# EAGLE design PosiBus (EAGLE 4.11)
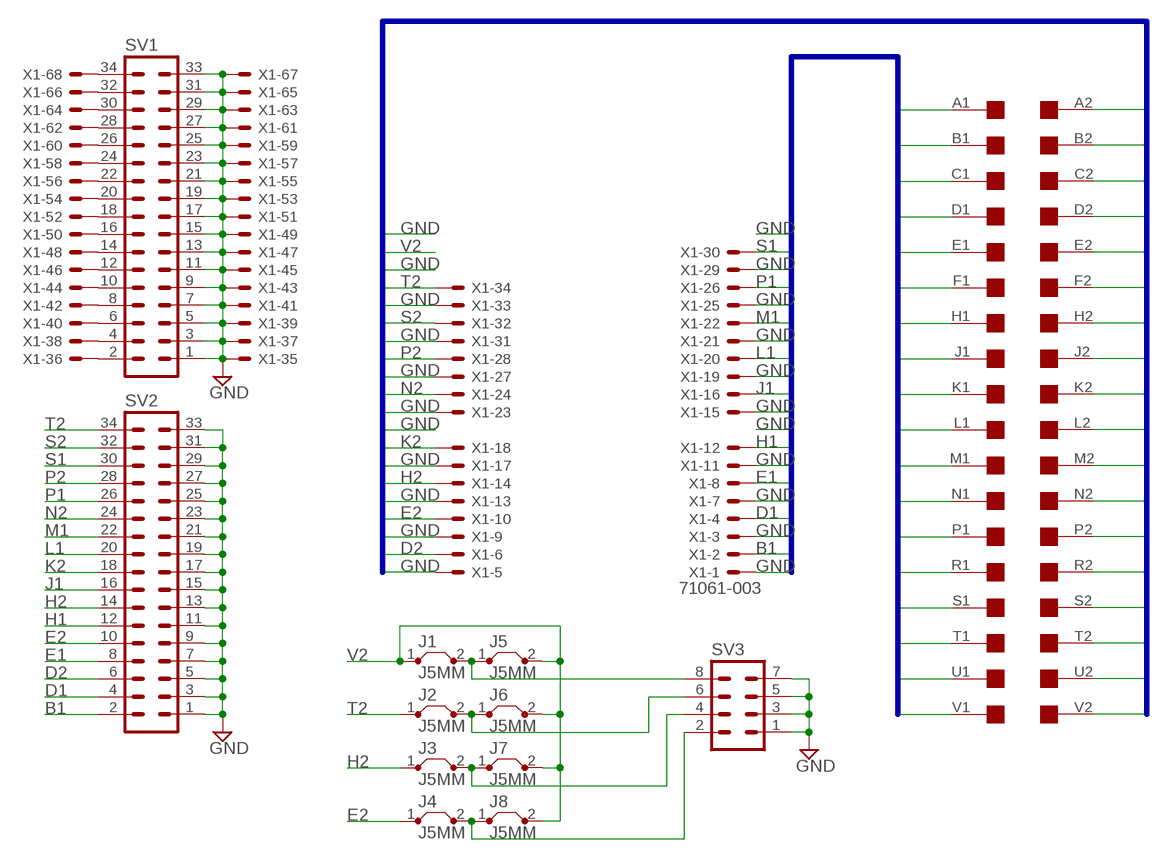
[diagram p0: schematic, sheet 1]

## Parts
J1  J5MM  [05]
J2  J5MM  [05]
J3  J5MM  [05]
J4  J5MM  [05]
J5  J5MM  [05]
J6  J5MM  [05]
J7  J5MM  [05]
J8  J5MM  [05]
SV1  ML34  [ML34]
SV2  ML34  [ML34]
SV3  MA04-2  [MA04-2]
U$1  DEC-FLIPCHIP  [DEC-FLIPCHIP]
X1  71061-003  [71061-0003]

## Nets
A2: U$1.A2
B1: SV2.2 U$1.B1 X1.2
B2: U$1.B2
D1: SV2.4 U$1.D1 X1.4
D2: SV2.6 U$1.D2 X1.6
E1: SV2.8 U$1.E1 X1.8
E2: J4.1 SV2.10 U$1.E2 X1.10
GND [Ground]: SV1.1 SV1.3 SV1.5 SV1.7 SV1.9 SV1.11 SV1.13 SV1.15 SV1.17 SV1.19 SV1.21 SV1.23 SV1.25 SV1.27 SV1.29 SV1.31 SV1.33 SV2.1 SV2.3 SV2.5 SV2.7 SV2.9 SV2.11 SV2.13 SV2.15 SV2.17 SV2.19 SV2.21 SV2.23 SV2.25 SV2.27 SV2.29 SV2.31 SV2.33 SV3.1 SV3.3 SV3.5 SV3.7 U$1.A1 U$1.C1 U$1.C2 U$1.F1 U$1.F2 U$1.J2 U$1.K1 U$1.L2 U$1.M2 U$1.N1 U$1.R1 U$1.R2 U$1.T1 U$1.U2 X1.1 X1.3 X1.5 X1.7 X1.9 X1.11 X1.13 X1.15 X1.17 X1.19 X1.21 X1.23 X1.25 X1.27 X1.29 X1.31 X1.33 X1.35 X1.37 X1.39 X1.41 X1.43 X1.45 X1.47 X1.49 X1.51 X1.53 X1.55 X1.57 X1.59 X1.61 X1.63 X1.65 X1.67
H1: SV2.12 U$1.H1 X1.12
H2: J3.1 SV2.14 U$1.H2 X1.14
J1: SV2.16 U$1.J1 X1.16
K2: SV2.18 U$1.K2 X1.18
L1: SV2.20 U$1.L1 X1.20
M1: SV2.22 U$1.M1 X1.22
N2: SV2.24 U$1.N2 X1.24
N$1: SV1.34 X1.68
N$2: SV1.4 X1.38
N$3: SV1.32 X1.66
N$4: SV1.30 X1.64
N$5: SV1.28 X1.62
N$6: SV1.26 X1.60
N$7: SV1.2 X1.36
N$8: J1.2 J5.1 SV3.8
N$9: J2.2 J6.1 SV3.6
N$10: J3.2 J7.1 SV3.4
N$11: SV1.24 X1.58
N$12: J4.2 J8.1 SV3.2
N$13: SV1.22 X1.56
N$14: SV1.20 X1.54
N$15: SV1.18 X1.52
N$16: SV1.16 X1.50
N$17: SV1.14 X1.48
N$23: SV1.12 X1.46
N$25: SV1.10 X1.44
N$27: SV1.8 X1.42
N$28: SV1.6 X1.40
P1: SV2.26 U$1.P1 X1.26
P2: SV2.28 U$1.P2 X1.28
S1: SV2.30 U$1.S1 X1.30
S2: SV2.32 U$1.S2 X1.32
T2: J2.1 SV2.34 U$1.T2 X1.34
U1: U$1.U1
V1: U$1.V1
V2: J1.1 J5.2 J6.2 J7.2 J8.2 U$1.V2

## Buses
A1,B1,C1,D1,E1,F1,H1,J1,K1,L1,M1,N1,P1,R1,S1,T1,U1,V1
A2,B2,C2,D2,E2,F2,H2,J2,K2,L2,M2,N2,P2,R2,S2,T2,U2,V2

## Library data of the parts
J1-J8 = jumper:J: Bridge
SV1 SV2 = con-harting-ml:ML34: HARTING
SV3 = con-lstb:MA04-2: PIN HEADER
U$1 = con-dec:DEC-FLIPCHIP: DEC Flip-Chip single card fingers
X1 = con-molex:71061-003: CONNECTOR 68-pin 1.27mm (.050 inch) pitch SCSI+ unshielded receptacle right angle all plastic

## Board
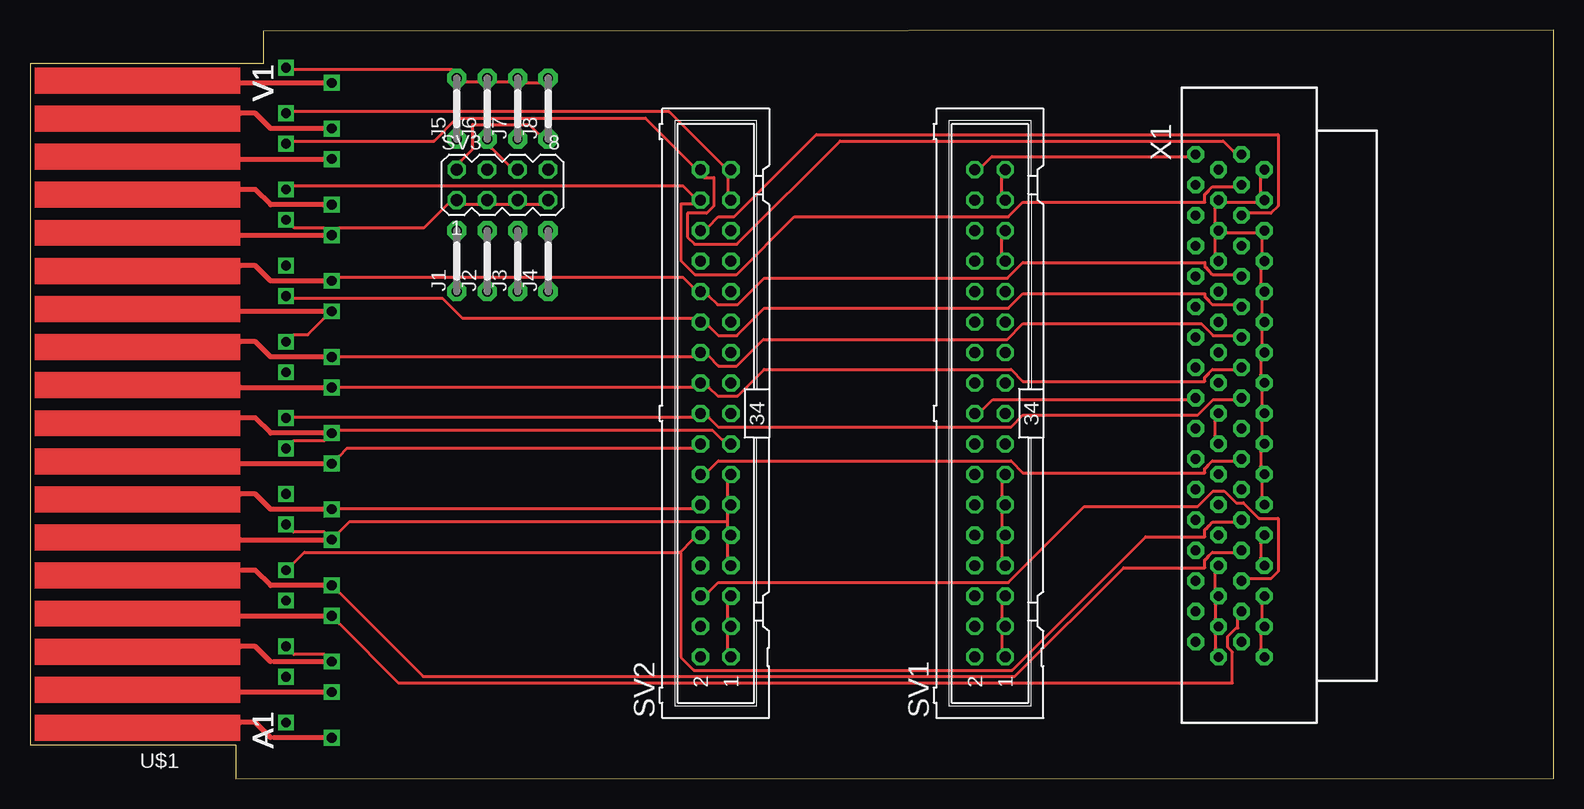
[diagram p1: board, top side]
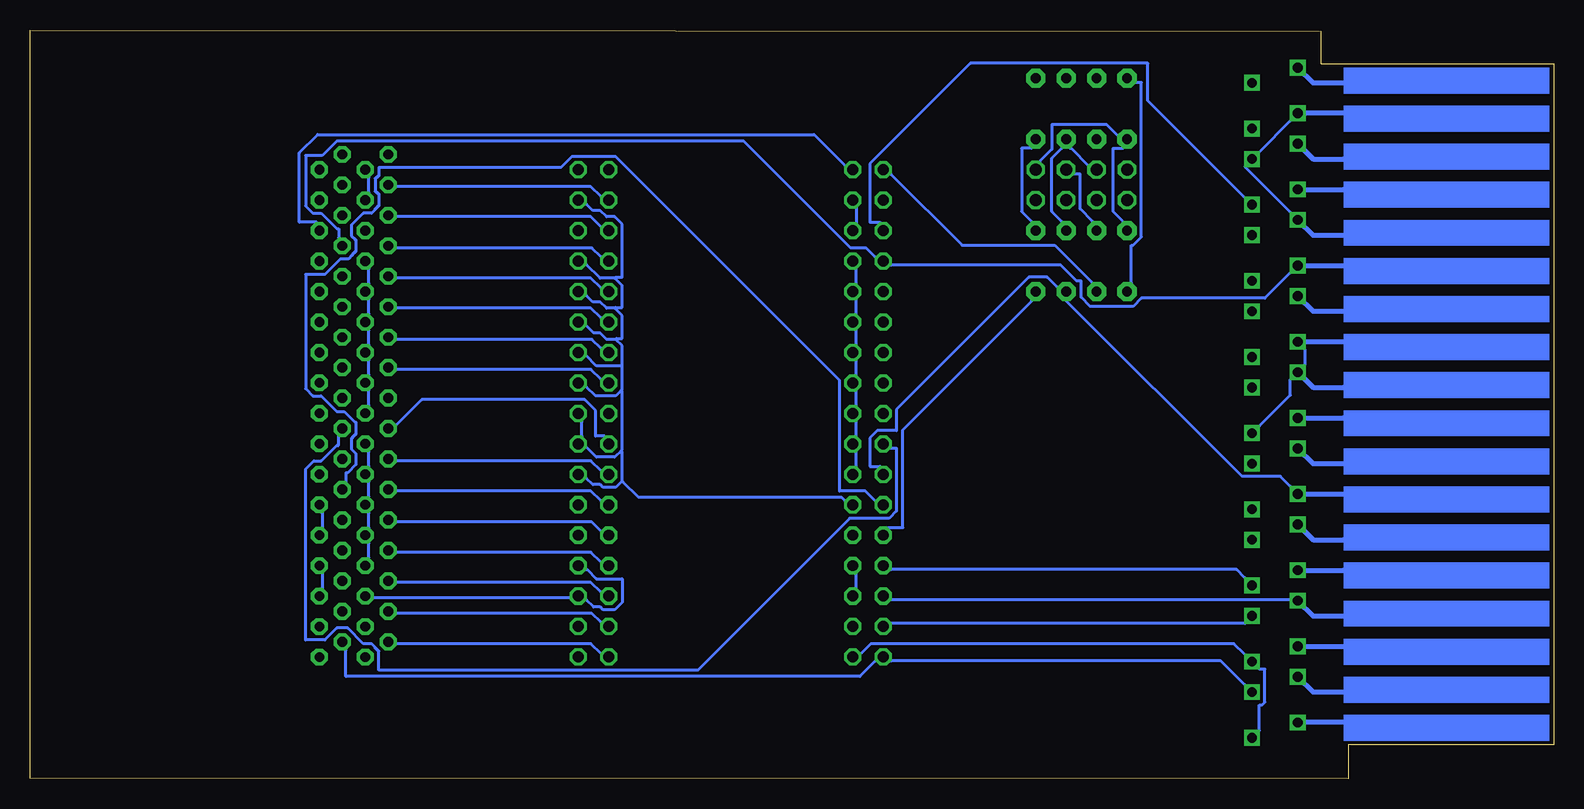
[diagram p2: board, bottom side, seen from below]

Size 126.98 x 62.45 mm. Coordinates in mm from the lower left corner, seen from the top.
Outline: 0,2.83 17.14,2.83 17.14,0 126.98,0.04 126.98,62.45 19.43,62.36 19.43,59.65 0,59.65 0,2.83
Copper layers (1*16): Top 0.035mm / dielectric 1.5mm / Bottom 0.035mm
Design rules "10mils": minimum track width 10mil, minimum drill 24mil, track to track 10mil, track to pad 10mil, pad to pad 10mil, via to via 10mil, smd to smd 10mil, copper to edge 40mil, drill to drill 10mil, minimum pad ring 10mil, minimum via ring 8mil, stop-mask expansion 0mil, vias tented up to drill 0mil, thermal gap 10mil

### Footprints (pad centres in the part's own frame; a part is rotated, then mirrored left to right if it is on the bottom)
05 = drill 0.813 pad 1.6 octagon: 1 -2.54,0; 2 2.54,0
ML34 = drill 0.914 octagon: 1 -20.32,-1.27; 2 -20.32,1.27; 3 -17.78,-1.27; 4 -17.78,1.27; 5 -15.24,-1.27; 6 -15.24,1.27; 7 -12.7,-1.27; 8 -12.7,1.27; 9 -10.16,-1.27; 10 -10.16,1.27; 11 -7.62,-1.27; 12 -7.62,1.27; 13 -5.08,-1.27; 14 -5.08,1.27; 15 -2.54,-1.27; 16 -2.54,1.27; 17 0,-1.27; 18 0,1.27; 19 2.54,-1.27; 20 2.54,1.27; 21 5.08,-1.27; 22 5.08,1.27; 23 7.62,-1.27; 24 7.62,1.27; 25 10.16,-1.27; 26 10.16,1.27; 27 12.7,-1.27; 28 12.7,1.27; 29 15.24,-1.27; 30 15.24,1.27; 31 17.78,-1.27; 32 17.78,1.27; 33 20.32,-1.27; 34 20.32,1.27
MA04-2 = drill 1.016 octagon: 1 -3.81,-1.27; 2 -3.81,1.27; 3 -1.27,-1.27; 4 -1.27,1.27; 5 1.27,-1.27; 6 1.27,1.27; 7 3.81,-1.27; 8 3.81,1.27
DEC-FLIPCHIP = drill 0.813 square: A1 -7.62,27.94; A2 -3.81,26.67; B1 -7.62,24.13; B2 -3.81,22.86; C1 -7.62,21.59; C2 -3.81,20.32; D1 -7.62,17.78; D2 -3.81,16.51; E1 -7.62,15.24; E2 -3.81,13.97; F1 -7.62,11.43; F2 -3.81,10.16; H1 -7.62,8.89; H2 -3.81,7.62; J1 -7.62,5.08; J2 -3.81,3.81; K1 -7.62,2.54; K2 -3.81,1.27; L1 -7.62,-1.27; L2 -3.81,-2.54; M1 -7.62,-3.81; M2 -3.81,-5.08; N1 -7.62,-7.62; N2 -3.81,-8.89; P1 -7.62,-10.16; P2 -3.81,-11.43; R1 -7.62,-13.97; R2 -3.81,-15.24; S1 -7.62,-16.51; S2 -3.81,-17.78; T1 -7.62,-20.32; T2 -3.81,-21.59; U1 -7.62,-22.86; U2 -3.81,-24.13; V1 -7.62,-26.67; V2 -3.81,-27.94
71061-0003 = drill 0.813 pad 1.397 octagon: 1 20.955,0; 2 19.685,-1.91; 3 18.415,0; 4 17.145,-1.91; 5 15.875,0; 6 14.605,-1.91; 7 13.335,0; 8 12.065,-1.91; 9 10.795,0; 10 9.525,-1.91; 11 8.255,0; 12 6.985,-1.91; 13 5.715,0; 14 4.445,-1.91; 15 3.175,0; 16 1.905,-1.91; 17 0.635,0; 18 -0.635,-1.91; 19 -1.905,0; 20 -3.175,-1.91; 21 -4.445,0; 22 -5.715,-1.91; 23 -6.985,0; 24 -8.255,-1.91; 25 -9.525,0; 26 -10.795,-1.91; 27 -12.065,0; 28 -13.335,-1.91; 29 -14.605,0; 30 -15.875,-1.91; 31 -17.145,0; 32 -18.415,-1.91; 33 -19.685,0; 34 -20.955,-1.91; 35 20.955,-3.82; 36 19.685,-5.73; 37 18.415,-3.82; 38 17.145,-5.73; 39 15.875,-3.82; 40 14.605,-5.73; 41 13.335,-3.82; 42 12.065,-5.73; 43 10.795,-3.82; 44 9.525,-5.73; 45 8.255,-3.82; 46 6.985,-5.73; 47 5.715,-3.82; 48 4.445,-5.73; 49 3.175,-3.82; 50 1.905,-5.73; 51 0.635,-3.82; 52 -0.635,-5.73; 53 -1.905,-3.82; 54 -3.175,-5.73; 55 -4.445,-3.82; 56 -5.715,-5.73; 57 -6.985,-3.82; 58 -8.255,-5.73; 59 -9.525,-3.82; 60 -10.795,-5.73; 61 -12.065,-3.82; 62 -13.335,-5.73; 63 -14.605,-3.82; 64 -15.875,-5.73; 65 -17.145,-3.82; 66 -18.415,-5.73; 67 -19.685,-3.82; 68 -20.955,-5.73

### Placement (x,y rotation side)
J1  35.55,43.18 90 top
J2  38.09,43.18 90 top
J3  40.63,43.18 90 top
J4  43.17,43.18 90 top
J5  35.55,55.88 90 top
J6  38.09,55.88 90 top
J7  40.63,55.88 90 top
J8  43.17,55.88 90 top
SV1  80.01,30.48 90 top
SV2  57.14,30.48 90 top
SV3  39.36,49.53 0 top
U$1  17.52,31.37 180 top
X1  102.87,31.11 270 top

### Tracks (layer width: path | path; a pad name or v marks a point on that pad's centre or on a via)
B1
  Bottom 0.254: U$1.B1 25.75,7.85 27.73,9.83 55.24,9.83 SV2.2 56.53,9.83 57.83,8.53 100.66,8.53 100.66,10.74 X1.2
D1
  Top 0.254: X1.4 100.66,13.34 100.66,12.57 100.5,12.57 99.82,11.89 99.82,10.97 100.2,10.59 100.2,8 30.7,8 25.75,12.95 U$1.D1
  Bottom 0.254: U$1.D1 25.75,12.95 55.24,12.95 SV2.4
D2
  Top 0.254: X1.6 101.65,16.69 103.4,16.69 104.01,17.3 104.01,21.72 102.41,21.72 101.11,23.01 100.5,23.01 99.51,24 98.6,24 97.3,22.71 87.85,22.71 81.53,16.38 57.37,16.38 56.53,15.54 SV2.6
  Bottom 0.254: U$1.D2 21.94,14.94 55.24,14.94 SV2.6
E1
  Top 0.254: X1.8 100.27,18.9 98.52,18.9 98.22,18.59 98.22,18.52 98.14,18.52 98.14,18.44 98.06,18.44 98.06,18.36 97.99,18.36 97.99,18.29 97.91,18.29 97.91,17.6 91.13,17.6 82.06,8.53 32.76,8.53 25.75,15.54 U$1.E1
  Bottom 0.254: U$1.E1 25.75,16.76 26.44,17.45 55.24,17.45 SV2.8
E2
  Top 0.254: 54.17,18.9 22.86,18.9 21.94,17.98 U$1.E2 | 54.17,18.9 55.24,19.96 SV2.10 | X1.10 100.27,21.41 98.52,21.41 98.22,21.11 98.22,21.03 98.14,21.03 98.14,20.95 98.06,20.95 98.06,20.88 97.99,20.88 97.99,20.8 97.91,20.8 97.91,20.19 92.96,20.19 81.83,9.07 55.32,9.07 54.25,10.13 54.25,18.82 54.17,18.9
  Bottom 0.254: J4.1 43.5,39.85 54.25,29.11 54.25,20.95 55.54,20.95 SV2.10
GND
  Top 0.254: U$1.J2 21.94,28.19 24.53,28.19 U$1.K1 25.75,29.03 56.92,29.03 57.68,28.27 57.75,28.27 SV2.15 | U$1.N1 24.53,38.41 23.16,37.03 21.94,37.03 U$1.M2 | U$1.C2 21.94,10.44 22.02,10.36 24.53,10.36 U$1.C1 | U$1.F2 21.94,20.57 24.53,20.57 U$1.F1 25.75,20.57 26.59,21.41 58.06,21.41 58.14,21.41 | SV2.1 58.14,10.82 58.14,12.04 SV2.3 58.14,13.34 58.14,14.55 SV2.5 | SV2.7 58.14,18.44 58.14,19.66 SV2.9 58.14,20.95 58.14,21.41 | 58.14,21.41 58.14,22.17 SV2.11 58.14,23.55 58.14,24.77 SV2.13 | SV3.7 42.44,47.93 41.37,47.93 SV3.5 39.92,47.93 38.78,47.93 SV3.3 37.41,47.93 36.27,47.93 SV3.1 34.82,47.93 32.84,45.95 25.75,45.95 U$1.R1 24.53,45.95 22.02,45.95 21.94,46.02 U$1.R2 | SV2.31 58.14,48.92 58.14,50.14 SV2.33 57.75,51.13 53.26,55.63 21.94,55.63 U$1.U2 | SV1.1 81,10.82 81,12.04 SV1.3 81,13.34 81,14.55 SV1.5 | SV1.7 81,18.44 81,19.66 SV1.9 81,20.95 81,22.17 SV1.11 81,23.55 81,24.77 SV1.13 | SV1.31 81,48.92 81,50.14 SV1.33 | SV1.27 81,43.81 81,45.03 SV1.29 | X1.1 102.56,10.82 102.56,12.04 X1.3 102.64,13.34 102.64,14.55 X1.5 | X1.9 102.56,19.66 102.56,18.44 X1.7 | X1.11 102.64,23.55 102.64,24.77 X1.13 102.56,26.06 102.56,27.28 X1.15 102.64,28.57 102.64,29.79 X1.17 102.64,31.17 102.64,32.38 X1.19 102.56,33.68 102.56,34.9 X1.21 102.64,36.2 102.64,37.41 X1.23 102.64,38.79 102.64,40.01 X1.25 102.56,41.3 102.56,42.52 X1.27 102.64,43.81 102.64,45.03 X1.29 102.18,45.57 99.74,45.57 X1.63 | X1.33 102.56,50.14 102.56,48.92 X1.31 102.18,48.08 99.74,48.08 X1.65 98.75,47.62 98.75,46.41 X1.63 | X1.35 98.75,10.82 98.75,12.04 X1.37 98.75,13.34 98.75,14.55 X1.39 98.75,15.93 98.75,17.14 X1.41
  Top 0.254: X1.51 98.75,29.79 98.75,28.57 X1.49 | X1.63 98.75,45.03 98.75,43.81 X1.61
  Bottom 0.254: U$1.M2 20.72,35.81 20.72,34.52 U$1.L2 21.94,33.3 21.94,32 24.53,29.41 U$1.K1 | U$1.A1 24.53,4.04 24.53,6.17 24.3,6.17 24.07,6.4 24.07,9.14 24.53,9.14 U$1.C1 25.75,10.36 26.67,11.28 56.92,11.28 57.75,10.44 SV2.1 | SV2.7 58.14,17.14 58.14,15.93 SV2.5 | SV2.13 58.14,26.06 58.14,27.28 SV2.15 58.14,28.57 58.14,29.79 SV2.17 58.14,31.17 58.14,32.38 SV2.19 58.14,33.68 58.14,34.9 SV2.21 58.14,36.2 58.14,37.41 SV2.23 58.14,38.79 58.14,40.01 SV2.25 58.14,41.3 58.14,42.52 SV2.27 | SV2.29 58.14,46.41 58.14,47.62 SV2.31 | U$1.U2 21.94,54.86 24.53,52.27 U$1.T1 25.75,51.05 21.94,47.24 U$1.R2 | SV1.7 80.62,17.45 80.54,17.45 79.78,16.69 77.64,16.69 77.64,14.71 78.25,14.1 79.24,14.1 79.47,14.33 80.01,14.33 80.62,14.94 SV1.5 81.91,15.09 98.37,15.09 X1.39 | SV1.17 81,29.79 81,28.57 SV1.15 80.62,27.66 79.78,26.82 78.25,26.82 77.72,27.36 | 77.72,32.38 77.64,32.46 77.64,34.44 | 77.72,32.38 78.18,31.93 79.85,31.93 80.62,32.69 SV1.19 | 77.64,34.44 79.78,34.44 80.62,35.28 SV1.21 | 78.18,36.65 78.94,36.65 79.47,37.19 80.01,37.19 80.62,37.8 SV1.23 | 78.18,36.65 77.64,36.12 77.64,34.52 77.64,34.44 | 78.25,39.24 78.94,39.24 79.47,39.78 80.08,39.78 80.62,40.31 SV1.25 | 78.25,39.24 77.64,38.63 77.64,36.73 78.1,36.73 78.18,36.65 | 77.72,27.36 77.64,27.43 77.64,32.31 77.72,32.38 | 78.25,41.76 79.47,41.76 80.62,42.9 SV1.27 | 78.25,41.76 77.64,41.15 77.64,39.32 78.18,39.32 78.25,39.24 | SV1.31 80.62,47.93 80.08,47.4 79.47,47.4 78.94,46.86 78.25,46.86 77.64,46.25 77.64,41.83 78.18,41.83 78.25,41.76 | 77.64,24.84 78.18,24.31 79.24,24.31 79.47,24.54 80.08,24.54 80.62,25.07 SV1.13
  Bottom 0.254: 77.64,24.84 77.64,27.28 77.72,27.36 | X1.7 102.64,17.14 102.64,15.93 X1.5 | X1.11 102.64,22.17 102.64,20.95 X1.9 | X1.41 98.75,18.44 98.75,19.66 X1.43 98.75,20.95 98.75,22.17 X1.45 98.75,23.55 98.75,24.77 X1.47 98.75,26.06 98.75,27.28 X1.49 | X1.51 98.75,31.17 98.75,32.38 X1.53 98.75,33.68 98.75,34.9 X1.55 98.75,36.2 98.75,37.41 X1.57 98.75,38.79 98.75,40.01 X1.59 98.75,41.3 98.75,42.52 X1.61 | X1.67 98.75,50.14 98.75,48.92 X1.65 | SV2.33 59.05,51.13 61.64,53.72 103.02,53.72 104.54,52.2 104.54,46.41 103.09,46.41 X1.29 | SV2.11 59.05,23.16 59.35,23.47 76.27,23.47 77.57,24.77 77.64,24.84
H1
  Top 0.254: U$1.H1 25.75,22.55 55.24,22.55 SV2.12
  Bottom 0.254: X1.12 100.66,24.77 100.66,25.53 100.5,25.53 99.82,26.21 99.82,27.13 100.2,27.51 100.2,28.42 100.12,28.42 100.12,28.5 100.05,28.5 100.05,28.57 99.97,28.57 99.97,28.65 99.89,28.65 99.89,28.73 99.82,28.73 99.82,29.72 99.89,29.72 100.81,30.63 101.42,30.63 102.71,31.93 103.4,31.93 104.01,32.54 104.01,42.06 102.41,42.06 101.11,43.36 100.43,43.36 100.12,43.66 100.12,43.74 100.05,43.74 100.05,43.81 99.97,43.81 99.97,43.89 99.89,43.89 99.89,43.97 99.82,43.97 99.82,44.96 99.89,44.96 100.2,45.26 100.2,46.18 99.21,47.17 98.52,47.17 98.22,47.47 98.22,47.55 98.14,47.55 98.14,47.62 98.06,47.62 98.06,47.7 97.99,47.7 97.99,47.78 97.91,47.78 97.91,48.77 97.99,48.77 97.99,48.84 98.06,48.84 98.06,48.92 98.14,48.92 98.14,49 98.22,49 98.22,50.06 98.14,50.06 98.14,50.14 98.06,50.14 98.06,50.22 97.99,50.22 97.99,50.29 97.91,50.29 97.91,50.98 82.75,50.98 81.83,51.89 78.18,51.89 59.51,33.22 59.51,24 57.37,24 56.53,23.16 SV2.12
H2
  Top 0.254: X1.14 100.27,26.52 98.52,26.52 98.22,26.21 98.22,26.14 98.14,26.14 98.14,26.06 98.06,26.06 98.06,25.98 97.99,25.98 97.99,25.91 97.91,25.91 97.91,25.53 82.75,25.53 81.76,26.52 57.37,26.52 56.53,25.68 SV2.14
  Bottom 0.254: U$1.H2 21.94,24.38 22.78,25.22 25.98,25.22 40.61,39.85 J3.1 41.37,41 42.21,41.83 43.73,41.83 54.78,30.79 54.78,29.03 56.38,29.03 56.99,28.42 56.99,26.06 56.15,26.06 SV2.14
J1
  Top 0.254: U$1.J1 25.75,26.9 26.44,27.58 55.24,27.58 SV2.16
  Bottom 0.254: X1.16 101.27,28.57 101.27,27.81 101.42,27.81 102.71,26.52 103.32,26.52 104.01,25.83 104.01,11.58 102.41,11.58 101.42,12.57 100.5,12.57 99.21,11.28 98.52,11.28 98.22,10.97 98.22,10.9 98.14,10.9 98.14,10.82 98.06,10.82 98.06,10.74 97.99,10.74 97.99,10.67 97.91,10.67 97.91,9.07 71.32,9.07 58.67,21.72 55.39,21.72 54.78,22.33 54.78,27.58 55.24,27.58 SV2.16
K2
  Top 0.254: U$1.K2 21.94,30.18 55.24,30.18 SV2.18 56.53,30.18 57.37,29.34 81.76,29.34 82.75,30.33 97.3,30.33 98.6,31.62 100.27,31.62 X1.18
L1
  Top 0.254: U$1.L1 25.75,32.69 55.24,32.69 SV2.20 56.53,32.69 57.3,31.93 58.97,31.93 61.18,34.14 81.76,34.14 82.75,33.15 97.91,33.15 97.91,33.53 97.99,33.53 97.99,33.6 98.06,33.6 98.06,33.68 98.14,33.68 98.14,33.76 98.22,33.76 98.22,33.83 98.52,34.14 100.27,34.14 X1.20
M1
  Top 0.254: U$1.M1 25.75,35.2 55.24,35.2 SV2.22 56.53,35.28 57.37,34.44 58.9,34.44 61.11,36.65 81.45,36.65 82.75,37.95 97.61,37.95 98.6,36.96 100.27,36.96 X1.22
N2
  Top 0.254: U$1.N2 21.94,40.08 34.36,40.08 36.04,38.41 55.24,38.41 SV2.24 56.53,37.8 57.37,36.96 58.9,36.96 61.18,39.24 81.53,39.24 82.75,40.46 97.91,40.46 97.91,40.16 97.99,40.16 97.99,40.08 98.06,40.08 98.06,40.01 98.14,40.01 98.14,39.93 98.22,39.93 98.22,39.85 98.52,39.55 100.27,39.55 X1.24
N$1
  Top 0.254: X1.68 96.46,51.89 80.16,51.89 79.4,51.13 SV1.34
N$2
  Bottom 0.254: X1.38 96.46,13.79 80.16,13.79 79.4,13.03 SV1.4
N$3
  Bottom 0.254: X1.66 96.46,49.38 80.23,49.38 79.4,48.54 SV1.32
N$4
  Bottom 0.254: X1.64 96.46,46.86 80.23,46.86 79.4,46.02 SV1.30
N$5
  Bottom 0.254: X1.62 96.46,44.27 80.16,44.27 79.4,43.51 SV1.28
N$6
  Bottom 0.254: X1.60 96.46,41.76 80.23,41.76 79.4,40.92 SV1.26
N$7
  Bottom 0.254: X1.36 96.46,11.28 80.23,11.28 79.4,10.44 SV1.2
N$8
  Bottom 0.254: SV3.8 42.82,51.51 41.83,52.5 41.83,54.56 37.26,54.56 36.34,53.65 J5.1 35.88,52.58 36.72,52.58 36.72,47.32 35.88,46.48 J1.2
N$9
  Top 0.254: SV3.6 39.92,51.13 38.48,52.58 38.4,52.58 J6.1
  Bottom 0.254: J2.2 38.4,46.48 39.47,47.55 39.47,50.44 39.92,50.44 SV3.6
N$10
  Bottom 0.254: SV3.4 38.78,51.13 40.23,52.58 40.3,52.58 J7.1 40.99,52.58 41.83,51.74 41.83,47.32 40.99,46.48 J3.2
N$11
  Bottom 0.254: X1.58 96.46,39.24 80.23,39.24 79.4,38.41 SV1.24
N$12
  Top 0.254: SV3.2 35.88,51.51 36.88,52.5 36.88,54.56 41.6,54.56 42.44,53.72 J8.1
  Bottom 0.254: J4.2 43.5,46.48 44.34,47.32 44.34,52.58 43.5,52.58 J8.1
N$13
  Bottom 0.254: X1.56 96.46,36.65 80.16,36.65 79.4,35.89 SV1.22
N$14
  Bottom 0.254: X1.54 96.46,34.14 80.23,34.14 79.4,33.3 SV1.20
N$15
  Top 0.254: X1.52 96.46,31.62 80.23,31.62 79.4,30.79 SV1.18
N$16
  Bottom 0.254: X1.50 96.46,29.49 94.33,31.62 80.77,31.62 79.85,30.71 79.85,28.57 79.09,28.57 SV1.16
N$17
  Bottom 0.254: X1.48 96.46,26.52 80.23,26.52 79.4,25.68 SV1.14
N$23
  Bottom 0.254: X1.46 96.46,24 80.23,24 79.4,23.16 SV1.12
N$25
  Bottom 0.254: X1.44 96.46,21.41 80.16,21.41 79.4,20.65 SV1.10
N$27
  Bottom 0.254: X1.42 96.46,18.9 80.23,18.9 79.4,18.06 SV1.8
N$28
  Bottom 0.254: X1.40 96.46,16.38 80.23,16.38 79.4,15.54 SV1.6
P1
  Top 0.254: U$1.P1 25.75,41.83 54.4,41.83 55.24,41 SV2.26 56.53,40.31 57.3,39.55 58.97,39.55 61.18,41.76 81.45,41.76 82.75,43.05 97.91,43.05 97.91,42.67 97.99,42.67 97.99,42.6 98.06,42.6 98.06,42.52 98.14,42.52 98.14,42.44 98.22,42.44 98.22,42.37 98.52,42.06 100.27,42.06 X1.26
P2
  Bottom 0.254: U$1.P2 21.94,42.22 24.07,40.08 34.36,40.08 35.05,39.4 38.63,39.4 39.39,40.16 39.39,41.53 39.77,41.53 41.07,42.82 55.24,42.82 SV2.28 56.53,43.51 57.3,44.27 58.59,44.27 67.51,53.19 101.42,53.19 102.64,51.97 104.01,51.97 104.01,47.78 103.4,47.17 102.71,47.17 101.42,45.87 101.27,45.87 101.27,45.11 X1.28
S1
  Top 0.254: X1.30 101.65,47.17 103.4,47.17 104.01,47.78 104.01,53.72 65.53,53.72 58.67,46.86 57.37,46.86 56.53,46.02 SV2.30
  Bottom 0.254: U$1.S1 25.75,48.46 33.83,56.54 33.83,59.66 48.61,59.66 56.99,51.28 56.99,46.41 56.15,46.41 SV2.30
S2
  Top 0.254: U$1.S2 21.94,49.45 54.4,49.45 55.24,48.62 SV2.32 55.24,47.93 54.25,47.93 54.25,43.2 55.39,42.06 58.9,42.06 63.7,46.86 81.53,46.86 82.75,48.08 97.91,48.08 97.91,48.77 97.99,48.77 97.99,48.84 98.06,48.84 98.06,48.92 98.14,48.92 98.14,49 98.22,49 98.22,49.07 98.52,49.38 100.27,49.38 X1.32
T2
  Top 0.254: U$1.T2 21.94,53.19 33.67,53.19 35.58,55.09 51.28,55.09 55.24,51.13 SV2.34 56.15,50.14 56.99,50.14 56.99,47.78 56.38,47.17 54.78,47.17 54.78,45.19 55.39,44.58 58.9,44.58 67.51,53.19 99.44,53.19 100.27,52.35 X1.34
  Bottom 0.254: J2.1 38.48,41.38 41.6,44.5 49.3,44.5 55.24,50.44 SV2.34
V2
  Top 0.254: U$1.V2 21.94,59.13 35.2,59.13 J5.2 36.34,58.14 37.33,58.14 J6.2 38.86,58.14 39.85,58.14 J7.2 41.37,58.06 42.44,58.06 J8.2
  Bottom 0.254: J1.1 35.2,41.38 35.2,44.5 35.05,44.5 34.36,45.19 34.36,58.06 34.82,58.06 J5.2

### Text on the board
tNames: V1 | V1 | V1 | V1 | V1 | V1 | V1 | V1 | V1 | V1 | V1 | V1 | V1 | V1 | V1 | V1 | V1 | V1 | V1 | V1 | V1 | V1 | V1 | V1 | V1 | V1 | V1 | V1 | V1 | V1 | V1 | V1 | A1 | A1 | A1 | A1 | A1 | A1 | A1 | A1 | A1 | A1 | A1 | A1 | A1 | A1 | A1 | A1 | A1 | A1 | A1 | A1 | A1 | A1 | A1 | A1 | A1 | A1 | A1 | A1 | A1 | A1 | A1 | A1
